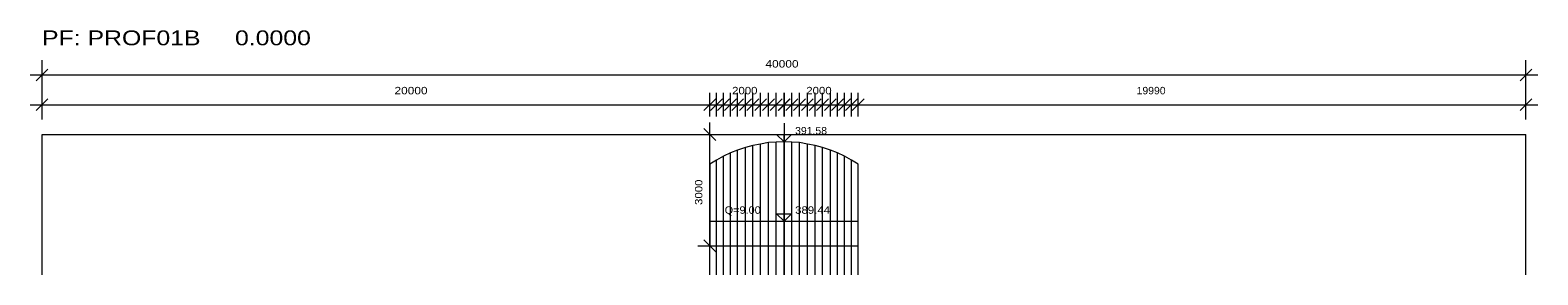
# Model space of a CAD drawing. Extents: x 7 to 442, y -393 to 441.
# Drawn here: x 281.31 to 321.95, y 396.2 to 402.79 of the extents above; entities that cross this region are included whole.
import ezdxf

# ---------------------------------------------------------------- set-up
doc = ezdxf.new("R2010")
doc.units = 0
doc.header["$LTSCALE"] = 0.08
doc.layers.add('7', color=7, linetype='Continuous', lineweight=13)

msp = doc.modelspace()

# ---------------------------------------------------------------- linework, layer by layer
at = {"layer": '7'}
for p, q in [((281.635, 400.38), (281.635, 401.98)), ((321.635, 400.38), (321.635, 401.98)), ((281.315, 401.58), (321.955, 401.58)), ((281.475, 401.42), (281.795, 401.74)), ((321.475, 401.42), (321.795, 401.74)), ((281.315, 400.78), (321.955, 400.78)), ((281.475, 400.62), (281.795, 400.94)), ((281.635, 400.46), (281.635, 401.1)), ((299.475, 400.62), (299.795, 400.94)), ((299.475, 400.62), (299.795, 400.94)), ((299.635, 400.46), (299.635, 401.1)), ((299.635, 400.46), (299.635, 401.1)), ((299.655, 400.62), (299.975, 400.94)), ((299.815, 400.46), (299.815, 401.1)), ((299.845, 400.62), (300.165, 400.94)), ((300.005, 400.46), (300.005, 401.1)), ((300.035, 400.62), (300.355, 400.94)), ((300.195, 400.46), (300.195, 401.1)), ((300.225, 400.62), (300.545, 400.94)), ((300.385, 400.46), (300.385, 401.1)), ((300.435, 400.62), (300.755, 400.94)), ((300.595, 400.46), (300.595, 401.1)), ((300.635, 400.62), (300.955, 400.94)), ((300.795, 400.46), (300.795, 401.1)), ((300.845, 400.62), (301.165, 400.94)), ((301.005, 400.46), (301.005, 401.1)), ((301.055, 400.62), (301.375, 400.94)), ((301.215, 400.46), (301.215, 401.1)), ((301.265, 400.62), (301.585, 400.94)), ((301.425, 400.46), (301.425, 401.1)), ((301.475, 400.62), (301.795, 400.94)), ((301.475, 400.62), (301.795, 400.94)), ((301.475, 400.62), (301.795, 400.94)), ((301.485, 400.62), (301.805, 400.94)), ((301.485, 400.62), (301.805, 400.94)), ((301.635, 400.46), (301.635, 401.1)), ((301.635, 400.46), (301.635, 401.1)), ((301.635, 400.46), (301.635, 401.1)), ((301.645, 400.46), (301.645, 401.1)), ((301.645, 400.46), (301.645, 401.1)), ((301.685, 400.62), (302.005, 400.94)), ((301.845, 400.46), (301.845, 401.1)), ((301.895, 400.62), (302.215, 400.94)), ((302.055, 400.46), (302.055, 401.1)), ((302.105, 400.62), (302.425, 400.94)), ((302.265, 400.46), (302.265, 401.1)), ((302.315, 400.62), (302.635, 400.94)), ((302.475, 400.46), (302.475, 401.1)), ((302.515, 400.62), (302.835, 400.94)), ((302.675, 400.46), (302.675, 401.1)), ((302.725, 400.62), (303.045, 400.94)), ((302.885, 400.46), (302.885, 401.1)), ((302.915, 400.62), (303.235, 400.94)), ((303.075, 400.46), (303.075, 401.1)), ((303.105, 400.62), (303.425, 400.94)), ((303.265, 400.46), (303.265, 401.1)), ((303.295, 400.62), (303.615, 400.94)), ((303.455, 400.46), (303.455, 401.1)), ((303.475, 400.62), (303.795, 400.94)), ((303.475, 400.62), (303.795, 400.94)), ((303.635, 400.46), (303.635, 401.1)), ((303.635, 400.46), (303.635, 401.1)), ((321.475, 400.62), (321.795, 400.94)), ((321.635, 400.46), (321.635, 401.1)), ((281.635, 396.2), (281.635, 399.98)), ((299.315, 399.98), (300.115, 399.98)), ((299.795, 399.82), (299.475, 400.14)), ((299.635, 396.82), (299.635, 400.3)), ((301.635, 396.2), (301.635, 399.98)), ((301.645, 396.2), (301.645, 399.98)), ((321.635, 396.2), (321.635, 399.98)), ((300.385, 396.2), (300.385, 399.56)), ((300.595, 396.2), (300.595, 399.63)), ((300.795, 396.2), (300.795, 399.68)), ((301.005, 396.2), (301.005, 399.72)), ((301.215, 396.2), (301.215, 399.76)), ((301.425, 396.2), (301.425, 399.77)), ((301.635, 396.2), (301.635, 399.78)), ((301.635, 399.78), (301.645, 399.78)), ((301.645, 396.2), (301.645, 399.78)), ((301.845, 396.2), (301.845, 399.77)), ((302.055, 396.2), (302.055, 399.76)), ((302.265, 396.2), (302.265, 399.72)), ((302.475, 396.2), (302.475, 399.68)), ((302.675, 396.2), (302.675, 399.63)), ((302.885, 396.2), (302.885, 399.56)), ((299.635, 396.2), (299.635, 399.18)), ((299.815, 396.2), (299.815, 399.29)), ((300.005, 396.2), (300.005, 399.39)), ((300.195, 396.2), (300.195, 399.48)), ((303.075, 396.2), (303.075, 399.48)), ((303.265, 396.2), (303.265, 399.39)), ((303.455, 396.2), (303.455, 399.29)), ((303.635, 396.2), (303.635, 399.18)), ((299.635, 397.643), (303.635, 397.643)), ((299.795, 396.82), (299.475, 397.14)), ((299.315, 396.98), (300.115, 396.98)), ((299.635, 396.2), (299.635, 396.98)), ((301.635, 396.2), (301.635, 396.98)), ((303.635, 396.2), (303.635, 396.98))]:
    msp.add_line(p, q, dxfattribs=at)
for points in [[(281.635, 399.98), (301.635, 399.98), (301.635, 399.78), (301.425, 399.77), (301.215, 399.76), (301.005, 399.72), (300.795, 399.68), (300.595, 399.63), (300.385, 399.56), (300.195, 399.48), (300.005, 399.39), (299.815, 399.29), (299.635, 399.18), (299.635, 396.98), (301.635, 396.98), (303.635, 396.98), (303.635, 399.18), (303.455, 399.29), (303.265, 399.39), (303.075, 399.48), (302.885, 399.56), (302.675, 399.63), (302.475, 399.68), (302.265, 399.72), (302.055, 399.76), (301.845, 399.77), (301.645, 399.78), (301.645, 399.98), (321.635, 399.98)], [(301.635, 400.28), (301.635, 399.78), (301.435, 399.98), (301.835, 399.98), (301.635, 399.78)], [(301.635, 398.143), (301.635, 397.643), (301.435, 397.843), (301.835, 397.843), (301.635, 397.643)]]:
    msp.add_lwpolyline(points, dxfattribs=at)

# ---------------------------------------------------------------- texts
for s, height, width, p in [('PF: PROF01B     0.0000', 0.4, 1.25, (281.635, 402.38)), ('40000', 0.2, 1.2, (301.135, 401.78)), ('20000', 0.2, 1.2, (291.135, 401.06)), ('2000', 0.2, 1.15, (300.235, 401.06)), ('2000', 0.2, 1.15, (302.235, 401.06)), ('19990', 0.2, 1.05, (311.14, 401.06)), ('391.58', 0.2, 1.05, (301.935, 399.98)), ('Q=9.00', 0.2, 1.1, (300.035, 397.843)), ('389.44', 0.2, 1.15, (301.935, 397.843))]:
    msp.add_text(s, height=height, dxfattribs=dict(at, width=width)).set_placement(p)
at = {"layer": '7', "width": 1.15}
msp.add_text('3000', height=0.2, rotation=90, dxfattribs=at).set_placement((299.435, 398.08))

doc.saveas('drawing.dxf')
